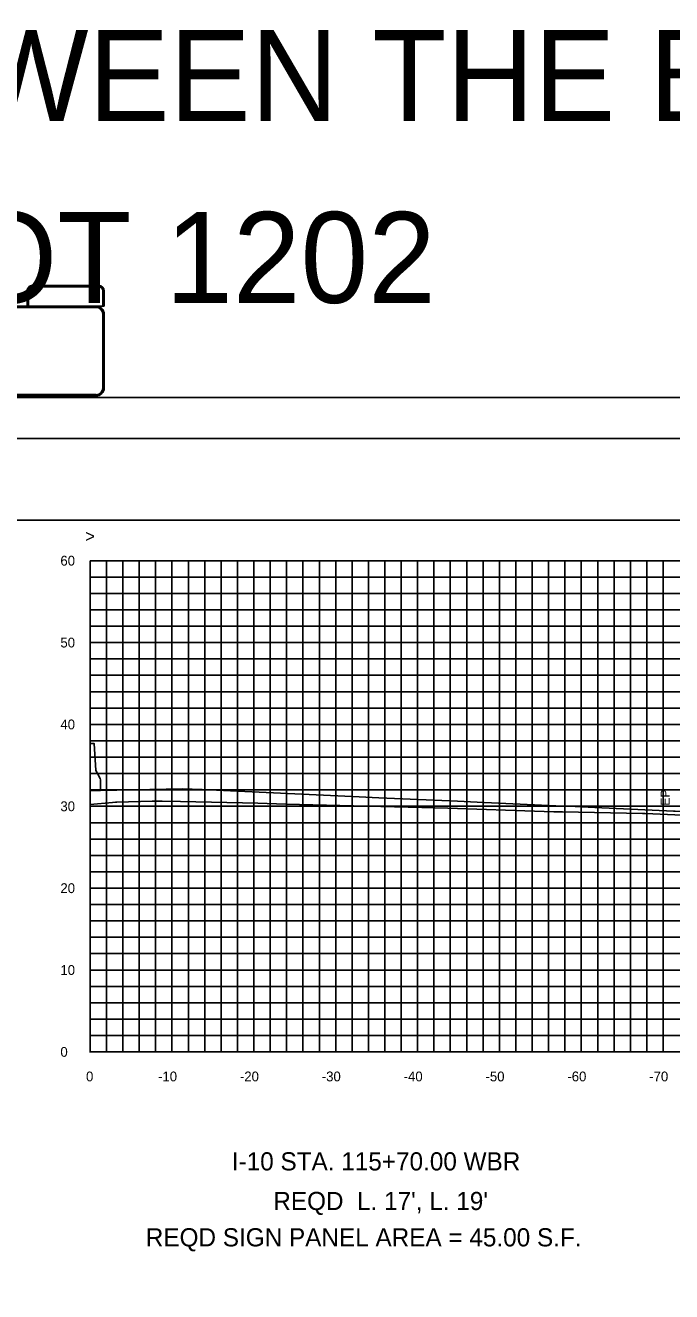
# Model space of a CAD drawing. Extents: x 1797809 to 2198143, y 249608 to 1237864.
# Drawn here: x 2195380.9 to 2195459.8, y 1237228.8 to 1237383.5 of the extents above; entities that cross this region are included whole.
import ezdxf

# ---------------------------------------------------------------- set-up
doc = ezdxf.new("R2010")
doc.units = 0
for name, color, linetype in [('10', 7, 'Continuous'), ('31', 7, 'Continuous'), ('60', 7, 'Continuous'), ('Default', 7, 'Continuous'), ('DESIGN - SHEET - Light Grid', 7, 'Continuous'), ('DESIGN - TRAFFIC CONTROL PERMANENT - Signs', 7, 'Continuous'), ('GSCOLORFILL', 7, 'Continuous'), ('GSOUTLINE', 7, 'Continuous'), ('GSSHT', 7, 'Continuous'), ('Level 45', 7, 'Continuous'), ('Level 55', 7, 'Continuous')]:
    doc.layers.add(name, color=color, linetype=linetype)

msp = doc.modelspace()

# ---------------------------------------------------------------- linework, layer by layer
at = {"layer": '60'}
for p, q in [((2195388.78, 1237258.11), (2195388.78, 1237318.11)), ((2195388.78, 1237258.05), (2195388.78, 1237258.11)), ((2195388.78, 1237258.11), (2195518.78, 1237258.11)), ((2195398.78, 1237258.05), (2195398.78, 1237258.11)), ((2195408.78, 1237258.05), (2195408.78, 1237258.11)), ((2195418.78, 1237258.05), (2195418.78, 1237258.11)), ((2195428.78, 1237258.05), (2195428.78, 1237258.11)), ((2195438.78, 1237258.05), (2195438.78, 1237258.11)), ((2195448.78, 1237258.05), (2195448.78, 1237258.11)), ((2195458.78, 1237258.05), (2195458.78, 1237258.11))]:
    msp.add_line(p, q, dxfattribs=at)
at = {"layer": 'Default'}
msp.add_lwpolyline([(2195388.78, 1237295.77), (2195389.28, 1237295.77), (2195389.46, 1237292.5), (2195390.01, 1237291.5), (2195390.03, 1237291.33), (2195390.03, 1237290.02), (2195388.78, 1237290.02)], dxfattribs=at)
at = {"layer": 'DESIGN - SHEET - Light Grid'}
msp.add_lwpolyline([(2195463.85, 1237286.89), (2195457.52, 1237287.18), (2195456.58, 1237287.22), (2195456.26, 1237287.24), (2195446.47, 1237287.43), (2195445.42, 1237287.45), (2195444.25, 1237287.49), (2195432.48, 1237287.89), (2195429.29, 1237287.97), (2195420.95, 1237288.17), (2195412.7, 1237288.39), (2195409.25, 1237288.48), (2195399.82, 1237288.69), (2195397.6, 1237288.74), (2195396.4, 1237288.74), (2195396.34, 1237288.74), (2195392.04, 1237288.61), (2195391.9, 1237288.61), (2195391.53, 1237288.58), (2195388.78, 1237288.34)], dxfattribs=at)
at = {"layer": 'DESIGN - TRAFFIC CONTROL PERMANENT - Signs'}
msp.add_lwpolyline([(2195491.58, 1237282.78), (2195472.05, 1237286.97), (2195471.65, 1237286.98), (2195470.05, 1237287.05), (2195462.91, 1237287.33), (2195461.12, 1237287.4), (2195461.06, 1237287.46), (2195461.05, 1237287.48), (2195460.25, 1237287.51), (2195460.05, 1237287.52), (2195450.45, 1237287.96), (2195448.05, 1237288.07), (2195445.65, 1237288.17), (2195436.05, 1237288.61), (2195433.65, 1237288.72), (2195424.05, 1237289.16), (2195421.65, 1237289.27), (2195412.05, 1237289.71), (2195402.45, 1237290.15), (2195400.05, 1237290.26), (2195398.05, 1237290.21), (2195390.03, 1237290.02), (2195388.78, 1237290.02)], dxfattribs=at)
at = {"layer": 'GSCOLORFILL'}
msp.add_lwpolyline([(2195216.29, 1237123.04), (2195538.79, 1237123.04), (2195538.79, 1237333.04), (2195216.29, 1237333.04)], close=True, dxfattribs=at)
at = {"layer": 'GSOUTLINE'}
for p, q in [((2195381.08, 1237349.22), (2195381.08, 1237351.07)), ((2195381.08, 1237351.07), (2195381.08, 1237349.22)), ((2195381.25, 1237351.07), (2195381.25, 1237349.38)), ((2195381.75, 1237351.73), (2195389.83, 1237351.73)), ((2195389.83, 1237351.73), (2195381.75, 1237351.73)), ((2195389.83, 1237351.57), (2195381.75, 1237351.57)), ((2195390.33, 1237349.38), (2195390.33, 1237351.07)), ((2195390.5, 1237351.07), (2195390.5, 1237349.22)), ((2195390.5, 1237349.22), (2195390.5, 1237351.07)), ((2195381.25, 1237349.38), (2195381.25, 1237349.22)), ((2195390.33, 1237349.22), (2195390.33, 1237349.38)), ((2195389.5, 1237349.22), (2195370, 1237349.22)), ((2195389.5, 1237349.05), (2195370, 1237349.05)), ((2195381.25, 1237349.22), (2195381.08, 1237349.22)), ((2195381.08, 1237349.22), (2195390.5, 1237349.22)), ((2195390.5, 1237349.22), (2195390.33, 1237349.22)), ((2195390.33, 1237339.22), (2195390.33, 1237348.22)), ((2195390.5, 1237339.22), (2195390.5, 1237348.22)), ((2195370, 1237338.39), (2195389.5, 1237338.39)), ((2195370, 1237338.22), (2195389.5, 1237338.22))]:
    msp.add_line(p, q, dxfattribs=at)
for centre, major_axis, start_param, end_param in [((2195381.75, 1237351.07), (0.666, 0), 1.570796, 3.141593), ((2195381.75, 1237351.07), (0.666, 0), 1.570796, 3.141593), ((2195381.75, 1237351.07), (0.5, 0), 1.570796, 3.141593), ((2195389.83, 1237351.07), (0.666, 0), 0, 1.570796), ((2195389.83, 1237351.07), (0.666, 0), 0, 1.570796), ((2195389.83, 1237351.07), (0.5, 0), 0, 1.570796), ((2195389.5, 1237348.22), (1, 0), 0, 1.570796), ((2195389.5, 1237348.22), (0.833, 0), 0, 1.570796), ((2195389.5, 1237339.22), (1, 0), 4.712389, 6.283185), ((2195389.5, 1237339.22), (0.833, 0), 4.712389, 6.283185)]:
    msp.add_ellipse(centre, major_axis=major_axis, ratio=0.999829, start_param=start_param, end_param=end_param, dxfattribs=at)
at = {"layer": 'GSSHT'}
for p, q in [((2195388.78, 1237318.11), (2195518.78, 1237318.11)), ((2195390.78, 1237258.11), (2195390.78, 1237318.11)), ((2195392.78, 1237258.11), (2195392.78, 1237318.11)), ((2195394.78, 1237258.11), (2195394.78, 1237318.11)), ((2195396.78, 1237258.11), (2195396.78, 1237318.11)), ((2195398.78, 1237258.11), (2195398.78, 1237318.11)), ((2195400.78, 1237258.11), (2195400.78, 1237318.11)), ((2195402.78, 1237258.11), (2195402.78, 1237318.11)), ((2195404.78, 1237258.11), (2195404.78, 1237318.11)), ((2195406.78, 1237258.11), (2195406.78, 1237318.11)), ((2195408.78, 1237258.11), (2195408.78, 1237318.11)), ((2195410.78, 1237258.11), (2195410.78, 1237318.11)), ((2195412.78, 1237258.11), (2195412.78, 1237318.11)), ((2195414.78, 1237258.11), (2195414.78, 1237318.11)), ((2195416.78, 1237258.11), (2195416.78, 1237318.11)), ((2195418.78, 1237258.11), (2195418.78, 1237318.11)), ((2195420.78, 1237258.11), (2195420.78, 1237318.11)), ((2195422.78, 1237258.11), (2195422.78, 1237318.11)), ((2195424.78, 1237258.11), (2195424.78, 1237318.11)), ((2195426.78, 1237258.11), (2195426.78, 1237318.11)), ((2195428.78, 1237258.11), (2195428.78, 1237318.11)), ((2195430.78, 1237258.11), (2195430.78, 1237318.11)), ((2195432.78, 1237258.11), (2195432.78, 1237318.11)), ((2195434.78, 1237258.11), (2195434.78, 1237318.11)), ((2195436.78, 1237258.11), (2195436.78, 1237318.11)), ((2195438.78, 1237258.11), (2195438.78, 1237318.11)), ((2195440.78, 1237258.11), (2195440.78, 1237318.11)), ((2195442.78, 1237258.11), (2195442.78, 1237318.11)), ((2195444.78, 1237258.11), (2195444.78, 1237318.11)), ((2195446.78, 1237258.11), (2195446.78, 1237318.11)), ((2195448.78, 1237258.11), (2195448.78, 1237318.11)), ((2195450.78, 1237258.11), (2195450.78, 1237318.11)), ((2195452.78, 1237258.11), (2195452.78, 1237318.11)), ((2195454.78, 1237258.11), (2195454.78, 1237318.11)), ((2195456.78, 1237258.11), (2195456.78, 1237318.11)), ((2195458.78, 1237258.11), (2195458.78, 1237318.11)), ((2195388.78, 1237316.11), (2195518.78, 1237316.11)), ((2195388.78, 1237314.11), (2195518.78, 1237314.11)), ((2195388.78, 1237312.11), (2195518.78, 1237312.11)), ((2195388.78, 1237310.11), (2195518.78, 1237310.11)), ((2195388.78, 1237308.11), (2195518.78, 1237308.11)), ((2195388.78, 1237306.11), (2195518.78, 1237306.11)), ((2195388.78, 1237304.11), (2195518.78, 1237304.11)), ((2195388.78, 1237302.11), (2195518.78, 1237302.11)), ((2195388.78, 1237300.11), (2195518.78, 1237300.11)), ((2195388.78, 1237298.11), (2195518.78, 1237298.11)), ((2195388.78, 1237296.11), (2195518.78, 1237296.11)), ((2195388.78, 1237294.11), (2195518.78, 1237294.11)), ((2195388.78, 1237292.11), (2195518.78, 1237292.11)), ((2195388.78, 1237290.11), (2195518.78, 1237290.11)), ((2195388.78, 1237288.11), (2195518.78, 1237288.11)), ((2195388.78, 1237286.11), (2195518.78, 1237286.11)), ((2195388.78, 1237284.11), (2195518.78, 1237284.11)), ((2195388.78, 1237282.11), (2195518.78, 1237282.11)), ((2195388.78, 1237280.11), (2195518.78, 1237280.11)), ((2195388.78, 1237278.11), (2195518.78, 1237278.11)), ((2195388.78, 1237276.11), (2195518.78, 1237276.11)), ((2195388.78, 1237274.11), (2195518.78, 1237274.11)), ((2195388.78, 1237272.11), (2195518.78, 1237272.11)), ((2195388.78, 1237270.11), (2195518.78, 1237270.11)), ((2195388.78, 1237268.11), (2195518.78, 1237268.11)), ((2195388.78, 1237266.11), (2195518.78, 1237266.11)), ((2195388.78, 1237264.11), (2195518.78, 1237264.11)), ((2195388.78, 1237262.11), (2195518.78, 1237262.11)), ((2195388.78, 1237260.11), (2195518.78, 1237260.11)), ((2195388.78, 1237258.11), (2195518.78, 1237258.11))]:
    msp.add_line(p, q, dxfattribs=at)
msp.add_lwpolyline([(2195203.79, 1237118.04), (2195543.79, 1237118.04), (2195543.79, 1237338.04), (2195203.79, 1237338.04)], close=True, dxfattribs=at)
at = {"layer": 'Level 45'}
msp.add_lwpolyline([(2195228.78, 1237133.05), (2195528.78, 1237133.05), (2195528.78, 1237323.05), (2195228.78, 1237323.05)], close=True, dxfattribs=at)

# ---------------------------------------------------------------- texts
at = {"layer": '10'}
for s, p in [('0', (2195388.28, 1237254.51)), ('-10', (2195397.08, 1237254.51)), ('-20', (2195407.08, 1237254.51)), ('-30', (2195417.08, 1237254.51)), ('-40', (2195427.08, 1237254.51)), ('-50', (2195437.08, 1237254.51)), ('-60', (2195447.08, 1237254.51)), ('-70', (2195457.08, 1237254.51))]:
    msp.add_text(s, height=1.2, dxfattribs=at).set_placement(p)
at = {"layer": '31'}
for s, p in [('60', (2195385.15, 1237317.51)), ('50', (2195385.15, 1237307.51)), ('40', (2195385.15, 1237297.51)), ('30', (2195385.15, 1237287.51)), ('20', (2195385.15, 1237277.51)), ('10', (2195385.15, 1237267.51)), ('0', (2195385.15, 1237257.51))]:
    msp.add_text(s, height=1.2, dxfattribs=at).set_placement(p)
at = {"layer": '60'}
msp.add_text('>', height=1.5, dxfattribs=at).set_placement((2195388.18, 1237320.36))
at = {"layer": 'Level 55'}
for s, height, p in [('2) SPECIAL DESIGN POSTS ARE NEEDED BECAUSE THE DISTANCE BETWEEN THE BOTTOM OF THE CENTER', 11.1046, (2194857.18, 1237371.81)), ("  OF THE SIGN AND TOP OF THE EXISTING GROUND EXCEEDS 14' - ALDOT 1202", 11.1046, (2194857.18, 1237349.6)), ('I-10 STA. 115+70.00 WBR', 2.2209, (2195406.09, 1237243.63)), (" REQD  L. 17', L. 19'", 2.2209, (2195410.33, 1237238.79)), ('REQD SIGN PANEL AREA = 45.00 S.F.', 2.2209, (2195395.58, 1237234.35))]:
    msp.add_text(s, height=height, dxfattribs=at).set_placement(p)
msp.add_text('EP', height=1.11, rotation=90, dxfattribs=at).set_placement((2195459.59, 1237288.19))

doc.saveas('drawing.dxf')
